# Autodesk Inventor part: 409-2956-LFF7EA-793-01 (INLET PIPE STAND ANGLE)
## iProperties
Shininess: 64.0
Angle Display Precision: 2
Document Length Units: 11272
Document Angle Units: 11279
Document Time Units: 11290
Document Mass Units: 11286
Document Length Units Precision: 3
Document Angle Units Precision: 2
Compacted: True
Created: 2002-04
Part Number: 409-2956-LFF7EA-793-01 (INLET PIPE STAND ANGLE)
Description: INLET PIPE STAND ANGLE
Document SubType Name: Modeling
Designer: S. Boerckel
Mass: 1815.49 g
Surface Area: 764.458 cm^2
Volume: 231.273 cm^3
Density: 7.85 g/cm^3
Cost Center: 2 x 2 x 1/4 ANGLE
Material: ASTM A36
Engineer: S. Boerckel
Density: 0.0
Volumn: 0.0
Area: 0.0
PropertySet Name: Model Information
Control State: 0
Master: False
Checked Out: False
length: 15.088 in
SMR: =<COST CENTER> - <MATERIAL>
Author: S. Boerckel
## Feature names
1. Extrusion1
